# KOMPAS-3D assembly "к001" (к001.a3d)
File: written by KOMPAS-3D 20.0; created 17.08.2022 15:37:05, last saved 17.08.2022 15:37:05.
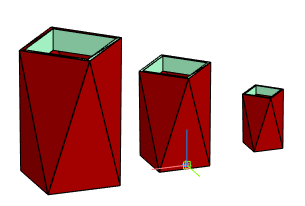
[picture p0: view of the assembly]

Document properties: Автор: artemsv220@gmail.com; Полное имя файла: \\192.168.2.25\новая общая папка\Медиа\Светильники\Кашпо\Кашпо и вазоны\DWG\к001.a3d

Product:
- Part/product: к001
  - Component [detail]: Cylinder122  | qty 6  | source file: \\192.168.2.25\новая общая папка\Медиа\Светильники\Кашпо\Кашпо и вазоны\DWG\Cylinder122.m3d
  - Component [detail]: Cylinder129  | qty 6  | source file: \\192.168.2.25\новая общая папка\Медиа\Светильники\Кашпо\Кашпо и вазоны\DWG\Cylinder129.m3d
  - Component [detail]: Cylinder135  | qty 6  | source file: \\192.168.2.25\новая общая папка\Медиа\Светильники\Кашпо\Кашпо и вазоны\DWG\Cylinder135.m3d

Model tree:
1. Поверхность без истории:1
2. Поверхность без истории:2
3. Поверхность без истории:3

Referenced files in \\192.168.2.25\новая общая папка\Медиа\Светильники\Кашпо\Кашпо и вазоны\DWG\: Cylinder135.m3d, Cylinder129.m3d, Cylinder122.m3d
